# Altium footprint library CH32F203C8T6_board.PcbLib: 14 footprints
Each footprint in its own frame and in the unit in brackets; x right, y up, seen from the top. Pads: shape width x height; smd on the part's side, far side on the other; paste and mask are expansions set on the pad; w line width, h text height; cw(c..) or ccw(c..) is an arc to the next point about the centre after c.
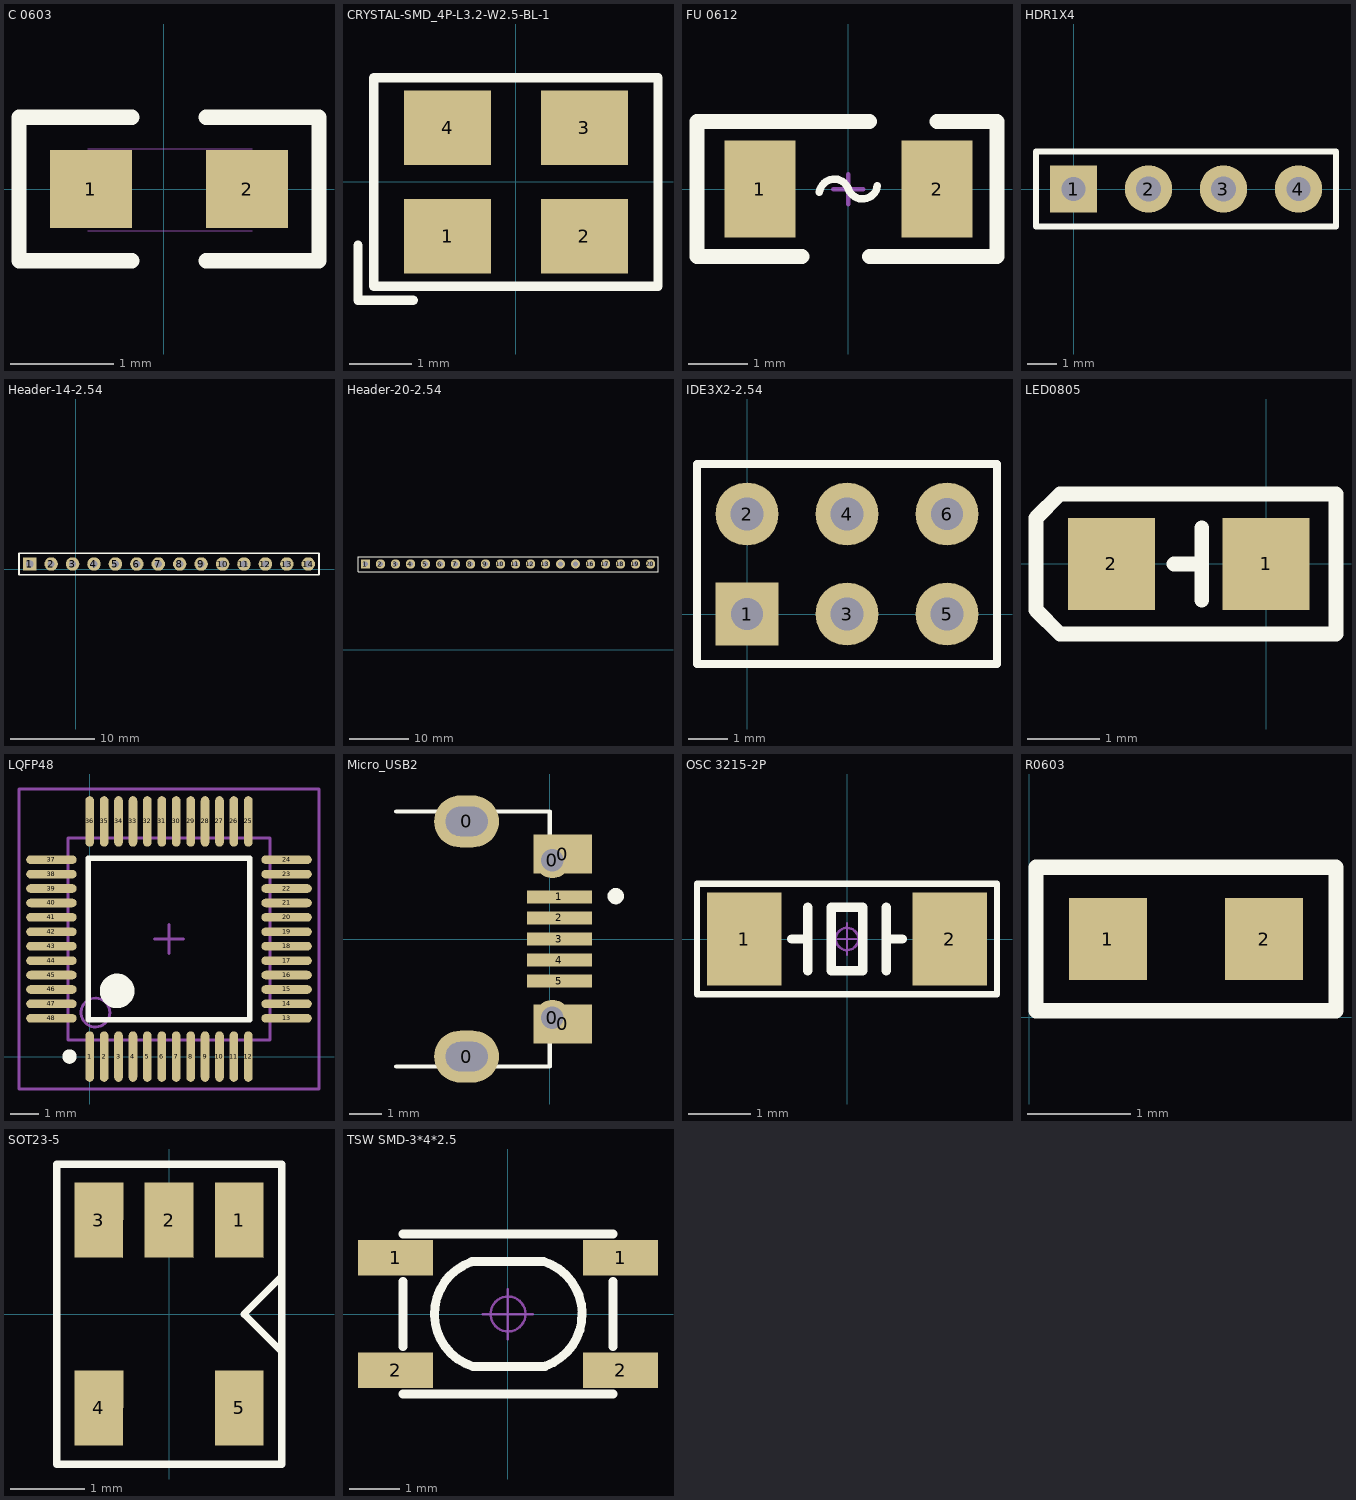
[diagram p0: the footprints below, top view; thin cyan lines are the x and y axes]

## C 0603 [mm] "无极性贴片电容"
pads (2):
  rect 0.8x0.76 smd: 1(-0.711,0) 2(0.809,0)
Top Overlay:
  lines w0.15: -0.311,-0.7 -1.411,-0.7 -1.411,0.7 -0.311,0.7 ; 0.409,-0.7 1.509,-0.7 1.509,0.7 0.409,0.7
Mechanical 13:
  lines w0.01: -0.742,-0.406 0.858,-0.406 ; -0.742,0.394 0.858,0.394
3D body "C 0603.STEP": height 0.81, standoff -0.01, extent -0.742,-0.41 0.858,0.41

## CRYSTAL-SMD_4P-L3.2-W2.5-BL-1 [mm]
pads (4):
  rect 1.4x1.2 smd: 1(-1.1,-0.875) 2(1.1,-0.875) 3(1.1,0.875) 4(-1.1,0.875)
Top Overlay:
  lines w0.152: -2.54,-1.016 -2.54,-1.778 -2.54,-1.905 -1.651,-1.905 ; -2.286,-1.679 2.286,-1.679 2.286,0 2.286,1.679 -2.286,1.679 -2.286,-1.679

## FU 0612 [mm] "贴片保险丝"
pads (2):
  rect 1.2x1.65 smd: 1(-1.5,0) 2(1.5,0)
Top Overlay:
  lines w0.127: -0.491,-0.058 cw(c-0.239,-0.087) 0,0 ccw(c0.239,0.087) 0.491,0.058
  lines w0.254: -0.786,-1.143 -2.564,-1.143 -2.564,1.143 -0.786,1.143 0.357,1.143 ; 0.357,-1.143 1.881,-1.143 ; 1.5,1.143 2.516,1.143 2.516,-1.143 1.627,-1.143
Mechanical 15:
  lines w0.076: -0.254,0 0.254,0 ; 0,-0.254 0,0.254
3D body "FU 0805.STEP": height 0.52, standoff 0, extent -1,-0.61 1,0.61

## HDR1X4 [mm] "Connector; Header; 4 Position"
pads (4):
  rect 1.6x1.6 hole 0.82: 1(0,0)
  round 1.6 hole 0.85: 2(2.54,0) 3(5.08,0)
  round 1.6 hole 0.82: 4(7.62,0)
Top Overlay:
  lines w0.203: -1.27,-1.27 8.89,-1.27 8.89,1.27 -1.27,1.27 -1.27,-1.27

## Header-14-2.54 [mm] "header 14 pin"
pads (14):
  rect 1.6x1.6 hole 0.85: 1(-5.461,0.635)
  round 1.6 hole 0.85: 2(-2.921,0.635) 3(-0.381,0.635) 4(2.159,0.635) 5(4.699,0.635) 6(7.239,0.635) 7(9.779,0.635) 8(12.319,0.635) 9(14.859,0.635) 10(17.399,0.635) 11(19.939,0.635) 12(22.479,0.635) 13(25.019,0.635) 14(27.559,0.635)
Top Overlay:
  lines w0.203: -6.73,-0.635 28.83,-0.635 28.83,1.905 -6.73,1.905 -6.73,-0.635

## Header-20-2.54 [mm] "header pin"
pads (20):
  rect 1.6x1.6 hole 0.82: 1(-72.771,14.478)
  round 1.6 hole 0.85: 2(-70.231,14.478) 3(-67.691,14.478) 4(-65.151,14.478) 5(-62.611,14.478) 6(-60.071,14.478) 7(-57.531,14.478) 8(-54.991,14.478) 9(-52.451,14.478) 10(-49.911,14.478) 11(-47.371,14.478) 12(-44.831,14.478) 13(-42.291,14.478) 16(-34.671,14.478) 17(-32.131,14.478) 18(-29.591,14.478) 19(-27.051,14.478)
  round 1.5 hole 0.85: 14(-39.751,14.478) 15(-37.211,14.478)
  round 1.6 hole 0.82: 20(-24.511,14.478)
Top Overlay:
  lines w0.203: -74.04,13.208 -23.24,13.208 -23.24,15.748 -74.04,15.748 -74.04,13.208

## IDE3X2-2.54 [mm]
pads (6):
  rect 1.6x1.6 hole 0.82: 1(0,0)
  round 1.6 hole 0.85: 2(0,2.54) 3(2.54,0) 4(2.54,2.54) 5(5.08,0)
  round 1.6 hole 0.82: 6(5.08,2.54)
Top Overlay:
  lines w0.2: 1.482,-1.27 6.35,-1.27 ; 6.35,-1.27 6.35,3.81 -1.27,3.81 -1.27,-1.27 6.35,-1.27

## LED0805 [mm]
pads (2):
  rect 1.2x1.27 smd: 1(0,0) 2(-2.134,0)
Top Overlay:
  lines w0.203: -1.27,0 -0.889,0 ; -0.889,-0.5 -0.889,0.5 ; -3.175,-0.635 -2.845,-0.965 -2.794,-0.965 0.965,-0.965 0.965,0.965 -2.845,0.965 -3.175,0.635 -3.175,-0.635

## LQFP48 [mm]
pads (48):
  oval 0.3x1.75 smd: 1(0,0) 2(0.5,0) 3(1,0) 4(1.5,0) 5(2,0) 6(2.5,0) 7(3,0) 8(3.5,0) 9(4,0) 10(4.5,0) 11(5,0) 12(5.5,0) 25(5.5,8.15) 26(5,8.15) 27(4.5,8.15) 28(4,8.15) 29(3.5,8.15) 30(3,8.15) 31(2.5,8.15) 32(2,8.15) 33(1.5,8.15) 34(1,8.15) 35(0.5,8.15) 36(0,8.15)
  oval 1.75x0.3 smd: 13(6.825,1.325) 14(6.825,1.825) 15(6.825,2.325) 16(6.825,2.825) 17(6.825,3.325) 18(6.825,3.825) 19(6.825,4.325) 20(6.825,4.825) 21(6.825,5.325) 22(6.825,5.825) 23(6.825,6.325) 24(6.825,6.825) 37(-1.325,6.825) 38(-1.325,6.325) 39(-1.325,5.825) 40(-1.325,5.325) 41(-1.325,4.825) 42(-1.325,4.325) 43(-1.325,3.825) 44(-1.325,3.325) 45(-1.325,2.825) 46(-1.325,2.325) 47(-1.325,1.825) 48(-1.325,1.325)
Top Overlay:
  circle w0.25: c-0.7,0 r0.125
  circle w0.6: c0.95,2.275 r0.3
  lines w0.2: -0.05,1.275 5.55,1.275 5.55,6.875 -0.05,6.875 -0.05,1.275
Mechanical 13:
  circle w0.1: c0.2,1.525 r0.5
  lines w0.1: -0.75,0.575 6.25,0.575 6.25,7.575 -0.75,7.575 -0.75,0.575
Mechanical 15:
  lines w0.1: 2.25,4.075 3.25,4.075 ; 2.75,3.575 2.75,4.575 ; -2.45,-1.125 7.95,-1.125 7.95,9.275 -2.45,9.275 -2.45,-1.125

## Micro_USB2 [mm] "Micro_USB Dock 5 Pin"
height 2.65
pads (11):
  oval 2x1.6 hole 0.9 slot 1.3 at 0 deg: 0(-2.564,-3.625) 0(-2.564,3.625)
  round 1.1 hole 0.7: 0(0.08,-2.425) 0(0.08,2.425)
  rect 1.8x1.2 smd: 0(0.4,-2.616) 0(0.4,2.616)
  rect 2x0.4 smd: 1(0.3,1.3) 2(0.3,0.65) 3(0.3,0) 4(0.3,-0.65) 5(0.3,-1.3)
Top Overlay:
  circle w0.25: c2.034,1.321 r0.125
  lines w0.127: -4.734,-3.937 -3.404,-3.937 ; -4.734,3.937 -3.454,3.937 ; -1.727,-3.937 0,-3.937 ; -1.651,3.937 0,3.937 ; 0,-3.9 0,-2.997 ; 0,2.972 0,3.9
3D body "User Library-MicroUSB-B_Molex_105017-0001.STEP": height 2.68, standoff -0.63, extent -5.201,-4.1 0.229,4.1

## OSC 3215-2P [mm] "3.2*1.5*0.6mm(长宽高)"
pads (2):
  rect 1.2x1.5 smd: 1(-1.65,0) 2(1.65,0)
Top Overlay:
  lines w0.1: -2.413,-0.889 -2.413,0.889 2.413,0.889 2.413,-0.889 -2.413,-0.889
  lines w0.152: -0.889,0 -0.635,0 ; -0.635,-0.508 -0.635,0.508 ; 0.635,-0.508 0.635,0.508 ; 0.635,0 0.889,0 ; -0.254,-0.508 0.254,-0.508 0.254,0.508 -0.254,0.508 -0.254,-0.508
Mechanical 15:
  circle w0.04: c0,0 r0.18
  lines w0.04: -0.254,0 0.254,0 ; 0,-0.254 0,0.254
3D body "OSC 3215-2.STEP": height 0.61, standoff -0.01, extent -1.6,-0.75 1.6,0.75

## R0603 [mm]
pads (2):
  rect 0.76x0.8 smd: 1(0.766,0.762) 2(2.286,0.762)
Top Overlay:
  lines w0.15: 0.066,0.062 2.986,0.062 2.986,1.462 0.066,1.462 0.066,0.062
3D body "RES0603.STEP": height 0.65, standoff 0.2, extent 0.749,0.348 2.349,1.168

## SOT23-5 [mil]
height 47.24
pads (5):
  rect 26x40 smd: 1(37.4,50) 2(0,50) 3(-37.4,50) 4(-37.4,-50) 5(37.4,-50)
Top Overlay:
  lines w4: 60,-20 40,0 60,20 ; -60,-80 -60,80 60,80 60,-80 -60,-80
  text "." at 70,49 h30

## TSW SMD-3*4*2.5 [mm] "3*4*2.5mm"
height 2.5
pads (4):
  rect 1.5x0.7 smd: 1(-2.25,1.125) 1(2.25,1.125) 2(-2.25,-1.125) 2(2.25,-1.125)
Top Overlay:
  lines w0.178: -2.1,-1.6 2.1,-1.6 ; -2.1,-0.65 -2.1,0.65 ; -2.1,1.6 2.1,1.6 ; -0.738,1.037 ccw(c-0.372,0) -0.7,-1.05 0.737,-1.05 ; -0.725,1.05 0.712,1.05 cw(c0.384,0) 0.75,-1.037 ; 2.1,-0.65 2.1,0.65
Mechanical 15:
  circle w0.05: c0,0 r0.35
  lines w0.05: -0.5,0 0.5,0 ; 0,-0.5 0,0.5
